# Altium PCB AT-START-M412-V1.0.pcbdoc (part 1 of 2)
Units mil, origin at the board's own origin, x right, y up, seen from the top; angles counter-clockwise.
Board outline 4079.45 x 3617.4 mil, 2 copper layers (Top Layer, Bottom Layer); 111 components, 104 nets, 441 pads, 691 vias.
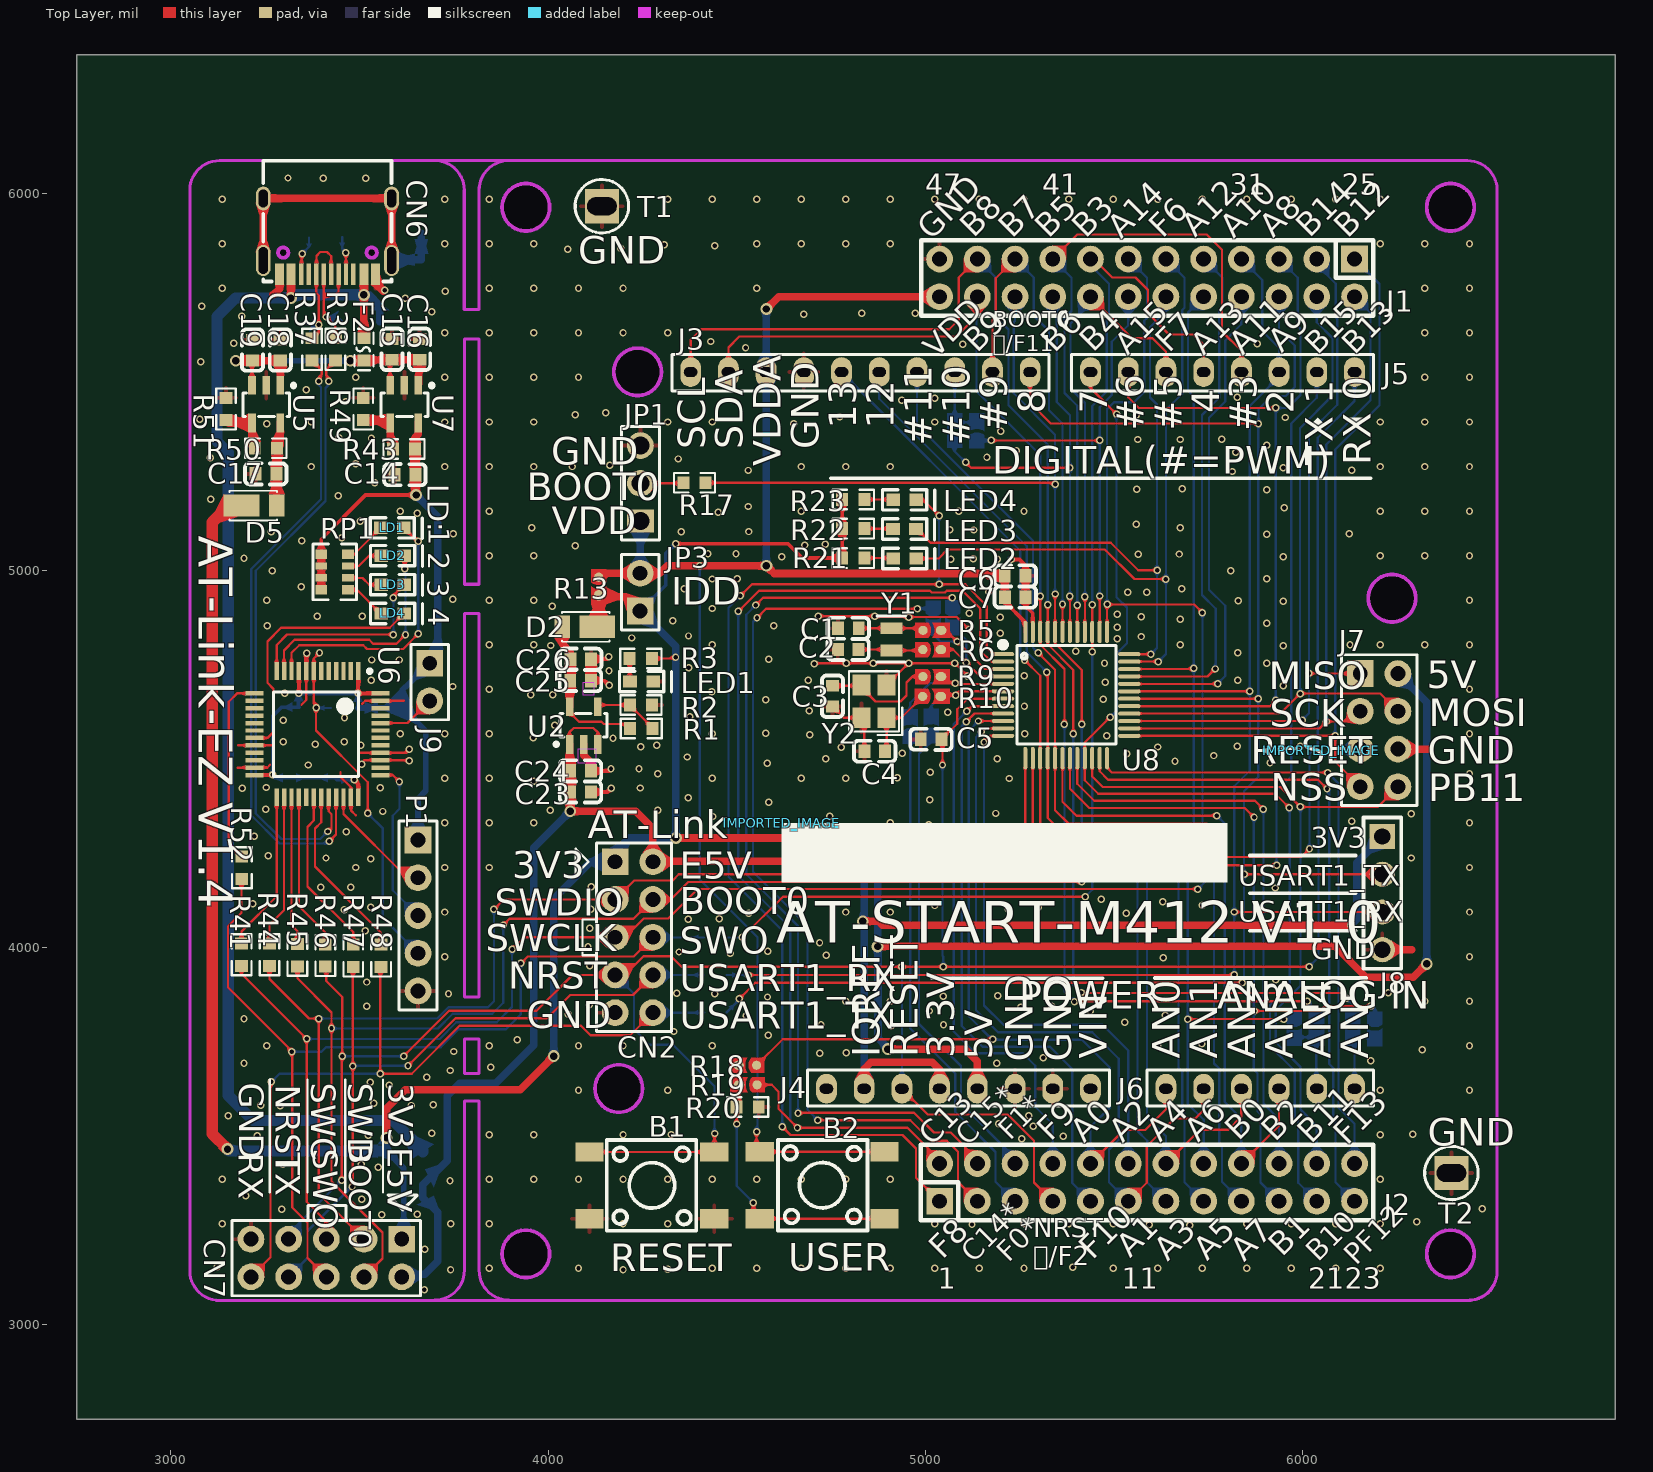
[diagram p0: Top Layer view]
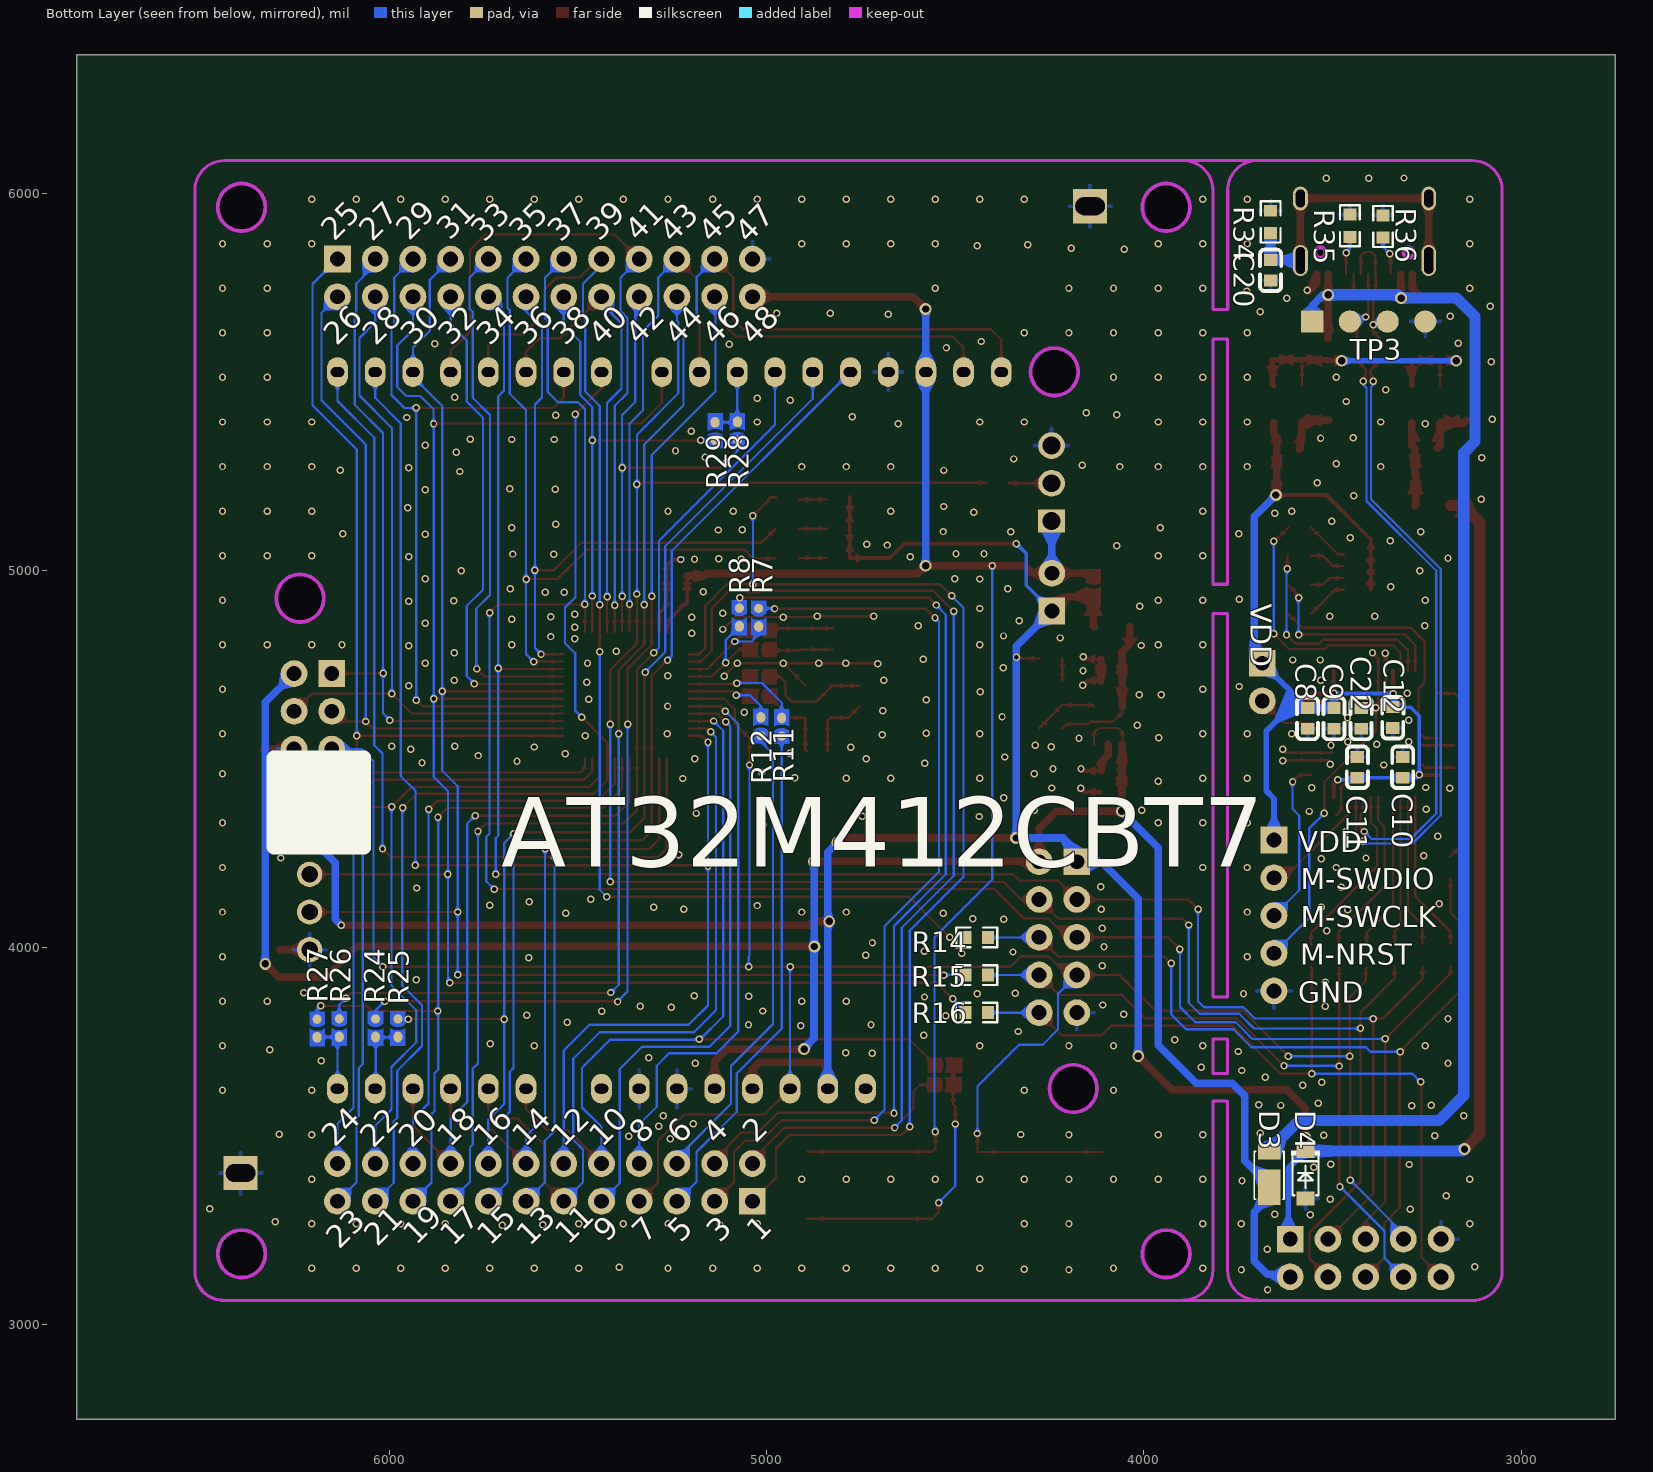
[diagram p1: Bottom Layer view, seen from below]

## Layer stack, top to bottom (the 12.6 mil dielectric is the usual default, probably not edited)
Top Layer: signal copper (thickness not stored)
Dielectric: dielectric 12.6, FR-4, Dk 4.8
Bottom Layer: signal copper (thickness not stored)

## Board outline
6829.45,2750 2750,2750 2750,6367.4 6829.45,6367.4
cut-out: 6455.12,5962.67 ccw(c6392.12,5962.67) 6329.13,5962.67 ccw(c6392.12,5962.67)
cut-out: 6455.12,3187.98 ccw(c6392.12,3187.98) 6329.13,3187.98 ccw(c6392.12,3187.98)
cut-out: 4003.92,3187.98 ccw(c3940.92,3187.98) 3877.93,3187.98 ccw(c3940.92,3187.98)
cut-out: 4250.26,3626.35 ccw(c4187.26,3626.35) 4124.27,3626.35 ccw(c4187.26,3626.35)
cut-out: 6300.26,4926.35 ccw(c6237.27,4925.79) 6174.28,4926.35 ccw(c6237.27,4926.91)
cut-out: 4300.26,5526.35 ccw(c4237.26,5526.35) 4174.27,5526.35 ccw(c4237.26,5526.35)
cut-out: 4003.93,5962.67 ccw(c3940.94,5962.44) 3877.95,5962.67 ccw(c3940.94,5962.89)

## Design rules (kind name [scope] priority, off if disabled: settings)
Clearance copperThickness1oz [All] p1: gap=7 ignorepadtopadclearanceinfootprint=FALSE except(6: Track-Track Track-SMDPad SMDPad-SMDPad Track-THPad SMDPad-THPad THPad-THPad Track-Via SMDPad-Via THPad-Via Via-Via Track-Fill SMDPad-Fill THPad-Fill Via-Fill Fill-Fill SMDPad-Region THPad-Region Via-Region Fill-Region Region-Region Track-Poly SMDPad-Poly THPad-Poly Via-Poly Fill-Poly Poly-Poly Track-Text SMDPad-Text THPad-Text Via-Text Fill-Text Region-Text Poly-Text Text-Text Track-Hole SMDPad-Hole THPad-Hole Via-Hole Fill-Hole Region-Hole Poly-Hole Text-Hole; 11.8: Track-Region Region-Poly Track-Sheet SMDPad-Sheet THPad-Sheet Via-Sheet Fill-Sheet Region-Sheet Poly-Sheet Text-Sheet Sheet-Hole)
DiffPairsRouting differentialPair [All] p1: maxuncoupledlength=10 maxlimit=6 mostfreqgap=6 toplayer_minwidth=5 toplayer_prefwidth=10 toplayer_maxwidth=100 bottomlayer_minwidth=5 bottomlayer_prefwidth=10 bottomlayer_maxwidth=100
PasteMaskExpansion pasteMaskExpansion [All] p1:
PlaneConnect innerPlane [All] p1: planeconnectstyle=Relief reliefexpansion=20 reliefentries=4 reliefconductorwidth=10 reliefairgap=10
PolygonConnect copperRegion [All] p1: connectstyle=Relief reliefentries=4 reliefconductorwidth=10 polygonreliefangle="90 Angle" airgapwidth=10
RoutingVias viaSize [All] p1: viastyle="Through Hole" holewidth=11.8 minholewidth=11.8 maxholewidth=27.6 width=19.7 minwidth=19.7 maxwidth=39.4
SolderMaskExpansion solderMaskExpansion [All] p1: useseparateexpansions=TRUE expansion=2 expansionbottom=2
Width copperThickness1oz [All] p1: maxlimit=100 minlimit=5 preferedwidth=6

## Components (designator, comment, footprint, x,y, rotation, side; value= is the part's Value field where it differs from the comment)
B1 "TS-1002S-05026C" KEY-SMD_4P-L6.0-W6.0-P4.50-LS9.0 4275.36,3369.64 r0 top
B2 "TSA063G60-250" KEY-SMD_4P-L6.1-W6.1-P4.50-LS9.0 4726.55,3369.99 r180 top
C1 "CL10C180JB8NNNC" C0603 4796.08,4846.54 r0 top
C2 "CL10C180JB8NNNC" C0603 4795.58,4790.46 r0 top
C3 "CL10C150JB8NNNC" C0603 4753.97,4666.49 r90 top
C4 "CL10C150JB8NNNC" C0603 4865.97,4520.49 r0 top
C5 "CC0603KRX7R9BB104" C0603 5015.49,4552.03 r0 top
C6 "CL10A475KO8NNNC" C0603 5238.29,4985.83 r180 top
C7 "CC0603KRX7R9BB104" C0603 5238.35,4929.24 r180 top
C8 "CL10A475KO8NNNC" C0603 3565.92,4607.82 r90 bottom
C9 "CC0603KRX7R9BB104" C0603 3495.92,4607.82 r90 bottom
C10 "CC0603KRX7R9BB104" C0603 3313.92,4477.82 r270 bottom
C11 "CC0603KRX7R9BB104" C0603 3433.92,4477.82 r270 bottom
C12 "CC0603KRX7R9BB104" C0603 3339.92,4609.82 r90 bottom
C14 "CL10A106KP8NNNC" C0603 3620.53,5253.61 r0 top
C15 "CL10A106KP8NNNC" C0603 3586.1,5585.92 r270 top
C16 "CC0603KRX7R9BB104" C0603 3659.3,5585.96 r270 top
C17 "CL10A106KP8NNNC" C0603 3251.92,5255.82 r0 top
C18 "CL10A106KP8NNNC" C0603 3290.1,5583.92 r270 top
C19 "CC0603KRX7R9BB104" C0603 3216.1,5583.92 r270 top
C20 "CC0603KRX7R9BB104" C0603 3663.92,5795.82 r90 bottom
C22 "CC0603KRX7R9BB104" C0603 3423.92,4607.82 r90 bottom
C23 "CL10A106KP8NNNC" C0603 4085.97,4412.49 r0 top
C24 "CC0603KRX7R9BB104" C0603 4085.97,4468.49 r0 top
C25 "CL10A106KP8NNNC" C0603 4086.25,4707.66 r0 top
C26 "CC0603KRX7R9BB104" C0603 4086.58,4764.74 r0 top
CN2 "CON10" HDR2X5 4177.67,4227.53 r270 top
CN6 "TYPEC-304-BCP16" USB-C-SMD_TYPEC-304-BCP16 3414.92,5885.82 r180 top
CN7 "CON10" HDR2X5 3612.1,3227.03 r180 top locked
D2 "DFLS130L-7" POWERDI-123_L2.8-W1.8-LS3.7-RD 4083.97,4850.49 r180 top
D3 "DFLS130L-7" POWERDI-123_L2.8-W1.8-LS3.7-RD 3667.92,3411.82 r90 bottom
D4 "SMF3.3A_C2759873" SOD-123FL_L2.8-W1.8-LS3.8-RD 3571.62,3397.74 r270 bottom
D5 "DFLS130L-7" POWERDI-123_L2.8-W1.8-LS3.7-RD 3233.92,5171.82 r0 top
F2 "BSMD0603-050-6V" F0603 3511.92,5585.82 r270 top
IMPORTED_IMAGE "IMPORTED_IMAGE" IMPORTED_IMAGE 6049.2,4522.45 r0 top
IMPORTED_IMAGE "IMPORTED_IMAGE" IMPORTED_IMAGE 4619.97,4329.49 r0 top
J1 "Header 12X2" HEAD2*12 6137.91,5825.49 r180 top locked
J2 "Header 12X2" HEAD2*12 5037.93,3327.39 r0 top locked
J3 "CON10" "HDR1X10 - 2#" 5277.93,5525.82 r180 top locked
J4 "CON8" "HDR1X8 - 2#" 4737.93,3625.82 r0 top locked
J5 "CON8" "HDR1X8 - 2#" 6137.93,5525.82 r180 top locked
J6 "CON6" "HDR1X6 -2#" 5637.93,3625.82 r0 top locked
J7 "Header 4X2" HDR2X4 6152.93,4726.39 r270 top locked
J8 "PZ2.54-1*4-WZ" HDR-TH_4P-P2.54-H-M-W7.7-P 6211.54,4144.37 r270 top locked
J9 "1X2P_2.54M" HDR1X2 3686.1,4754.03 r270 top
JP1 "2.54-1*3P针" HDR-TH_3P-P2.54-V-M-1 4244.82,5230.95 r90 top
JP3 "1X2P_2.54M" HDR1X2 4243.97,4892.49 r90 top
LD1 "RED" LED0603 3556.14,5112.82 r0 top
LD2 "GREEN" LED0603 3557.1,5038.72 r0 top
LD3 "BLUE" LED0603 3557.14,4961.82 r0 top
LD4 "YELLOW" LED0603 3557.1,4885.82 r0 top
LED1 "RED" LED0603 4217.22,4705.31 r0 top
LED2 "RED" LED0603 4914.8,5031.55 r0 top
LED3 "YELLOW" LED0603 4914.43,5109.54 r0 top
LED4 "GREEN" LED0603 4914.61,5187.03 r0 top
P1 "Header 5" HDR1X5 3655.1,4285.03 r270 top
R1 "0603WAF5102T5E" R0603 4246.78,4580.68 r0 top
R2 "0603WAF1502T5E" R0603 4246.14,4642.98 r0 top
R3 "0603WAF1001T5E" R0603 4245.97,4766.49 r0 top
R5 "0603WAF0000T5E" SB-PAD_2 5019.42,4841.02 r0 top
R6 "0603WAF0000T5E" SB-PAD_2 5018.84,4789.96 r0 top
R7 "SB_PAD" SB-PAD_2 5021.33,4873.81 r270 bottom
R8 "SB_PAD" SB-PAD_2 5072.35,4874.25 r270 bottom
R9 "0603WAF0000T5E" SB-PAD_2 5019.02,4718.48 r0 top
R10 "0603WAF0000T5E" SB-PAD_2 5018.49,4665.95 r0 top
R11 "SB_PAD" SB-PAD_2 4960.34,4586.25 r90 bottom
R12 "SB_PAD" SB-PAD_2 5015.44,4587.74 r90 bottom
R13 "0603WAF0000T5E" SB-PAD_2 4133.97,4956.49 r270 top
R14 "0603WAF4700T5E" R0603 4443.07,4026.98 r180 bottom
R15 "0603WAF4700T5E" R0603 4443.1,3927.07 r180 bottom
R16 "0603WAF4700T5E" R0603 4443.46,3828.11 r180 bottom
R17 "0603WAF3301T5E" R0603 4387.97,5232.49 r180 top
R18 "0603WAF0000T5E" SB-PAD_2 4527.17,3688.08 r180 top
R19 "SB_PAD" SB-PAD_2 4528.62,3636.15 r180 top
R20 "0603WAF1003T5E" R0603 4528.75,3577.36 r0 top
R21 "0603WAF1001T5E" R0603 4809.4,5032.65 r180 top
R22 "0603WAF1001T5E" R0603 4809.4,5110.65 r180 top
R23 "0603WAF1001T5E" R0603 4809.4,5188.14 r180 top
R24 "SB_PAD" SB-PAD_2 6036.99,3785.48 r270 bottom
R25 "0603WAF0000T5E" SB-PAD_2 5977.56,3785.51 r270 bottom
R26 "SB_PAD" SB-PAD_2 6133.09,3785.81 r270 bottom
R27 "0603WAF0000T5E" SB-PAD_2 6192.02,3784.58 r270 bottom
R28 "SB_PAD" SB-PAD_2 5077.61,5371.23 r90 bottom
R29 "0603WAF0000T5E" SB-PAD_2 5136.87,5370.02 r90 bottom
R34 "RC0603FR-071ML" R0603 3663.92,5923.82 r90 bottom
R35 "0603WAF5101T5E" R0603 3453.92,5913.82 r90 bottom
R36 "0603WAF5101T5E" R0603 3365.92,5911.82 r90 bottom
R37 "0603WAF0000T5E" R0603 3373.92,5585.82 r270 top
R38 "0603WAF0000T5E" R0603 3435.92,5585.82 r270 top
R41 "0603WAF330JT5E" R0603 3187.3,3981.07 r270 top
R43 "0603WAF4702T5E" R0603 3617.92,5321.82 r180 top
R44 "0603WAF330JT5E" R0603 3261.3,3981.07 r270 top
R45 "0603WAF330JT5E" R0603 3335.3,3980.07 r270 top
R46 "0603WAF330JT5E" R0603 3409.3,3979.07 r270 top
R47 "0603WAF330JT5E" R0603 3483.3,3978.07 r270 top
R48 "0603WAF330JT5E" R0603 3557.3,3978.07 r270 top
R49 "0603WAF1502T5E" R0603 3509.92,5427.82 r90 top
R50 "0603WAF5102T5E" R0603 3251.92,5323.82 r180 top
R51 "0603WAF1502T5E" R0603 3145.92,5427.82 r90 top
R52 "0603WAF330JT5E" R0603 3187.92,4211.82 r270 top
RP1 "4D03WGJ0102T5E" RES-ARRAY-SMD_0603-8P-L3.2-W1.6-BL 3433.92,4995.82 r270 top
T1 "Test point" TestPoint 4142.64,5965.57 r0 top
T2 "Test point" TestPoint 6394.79,3402.35 r0 top
TP3 "1X4P_2.54F" "HDR1X4 - TOP" 3553.92,5659.82 r0 bottom
U2 "RT9080N-08GJ5" SOT-23-5 4157,4603.45 r90 top
U5 "RT9080N-08GJ5" SOT-23-5 3189.92,5425.82 r270 top
U6 "AT32F403ACCT7" "LQFP48 - 2" 3496.84,4733.03 r270 top locked
U7 "RT9080N-08GJ5" SOT-23-5 3555.92,5425.82 r270 top
U8 "AT32M412CxT7" LQFP-48_L7.0-W7.0-P0.50-LS9.0-BL 5373.54,4669.59 r270 top locked
Y1 "32.768KHz" "XTAL_SOP - FC-12M" 4910.33,4846.79 r270 top
Y2 "CJ13-080001210B20" CRYSTAL-SMD_4P-L3.2-W2.5-BL 4863.97,4652.49 r90 top

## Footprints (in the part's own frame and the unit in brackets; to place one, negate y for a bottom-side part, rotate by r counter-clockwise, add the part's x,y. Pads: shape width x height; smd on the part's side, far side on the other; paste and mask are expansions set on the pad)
C0603 [mm]
  rect 0.8x0.9 smd: 1(-0.7,0) 2(0.7,0)
  silkscreen extent -1.41,-0.71 1.39,0.72
CRYSTAL-SMD_4P-L3.2-W2.5-BL [mm]
  rect 1.4x1.2 smd: 1(-1.1,-0.85) 2(1.1,-0.85) 3(1.1,0.85) 4(-1.1,0.85)
  silkscreen extent -2.26,-1.91 2.03,1.68
F0603 [mil]
  rect 31.75x34.02 smd: 1(-29.66,0) 2(29.66,0)
  silkscreen extent -55,-25 55,25
HDR1X2 [mm]
  rect 1.8x1.8 hole 1: 1(0,0)
  round 1.8 hole 1: 2(2.54,0)
  silkscreen extent -1.27,-1.27 3.81,1.27
"HDR1X4 - TOP" [mm]
  rect 1.5x1.5 smd: 1(0,0)
  round 1.5 smd: 2(-2.54,0) 3(-5.08,0) 4(-7.62,0)
HDR1X5 [mm]
  rect 1.8x1.8 hole 1: 1(0,0)
  round 1.8 hole 1: 2(2.54,0) 3(5.08,0) 4(7.62,0) 5(10.16,0)
  silkscreen extent -1.27,-1.27 11.43,1.27
"HDR1X6 -2#" [mm]
  oval 1.4x2 hole 0.65 slot 0.9 at 0 deg: 1(0,0) 2(2.54,0) 3(5.08,0) 4(7.62,0) 5(10.16,0) 6(12.7,0)
  silkscreen extent -1.27,-1.17 13.97,1.27
"HDR1X8 - 2#" [mm]
  oval 1.4x2 hole 0.65 slot 0.9 at 0 deg: 1(0,0) 2(2.54,0) 3(5.08,0) 4(7.62,0) 5(10.16,0) 6(12.7,0) 7(15.24,0) 8(17.78,0)
  silkscreen extent -1.27,-1.17 19.05,1.27
"HDR1X10 - 2#" [mm]
  oval 1.4x2 hole 0.65 slot 0.9 at 0 deg: 1(0,0) 2(2.54,0) 3(5.08,0) 4(7.62,0) 5(10.16,0) 6(12.7,0) 7(15.24,0) 8(17.78,0) 9(20.32,0) 10(22.86,0)
  silkscreen extent -1.27,-1.17 24.1,1.27
HDR2X4 [mm]
  rect 1.8x1.8 hole 1: 1(0,0)
  round 1.8 hole 1: 2(0,2.54) 3(2.54,0) 4(2.54,2.54) 5(5.08,0) 6(5.08,2.54) 7(7.62,0) 8(7.62,2.54)
  silkscreen extent -1.27,-1.27 8.89,3.81
HDR2X5 [mm]
  rect 1.8x1.8 hole 1: 1(0,0)
  round 1.8 hole 1: 2(0,2.54) 3(2.54,0) 4(2.54,2.54) 5(5.08,0) 6(5.08,2.54) 7(7.62,0) 8(7.62,2.54) 9(10.16,0) 10(10.16,2.54)
  silkscreen extent -1.27,-1.27 11.43,3.81
HDR-TH_3P-P2.54-V-M-1 [mm]
  rect 1.575x1.8 hole 1.2: 1(-2.54,0)
  round 1.8 hole 1.2: 2(0,0) 3(2.54,0)
  silkscreen extent -3.81,-1.27 3.81,1.27
HDR-TH_4P-P2.54-H-M-W7.7-P [mm]
  rect 1.7x1.7 hole 1.1: 1(-3.81,0)
  round 1.7 hole 1.1: 2(-1.27,0) 3(1.27,0) 4(3.81,0)
  silkscreen extent -5.09,-1.27 5.09,1.27
HEAD2*12 [mm]
  rect 1.8x1.8 hole 1: 1(0,0)
  round 1.8 hole 1: 2(0,2.54) 3(2.54,0) 4(2.54,2.54) 5(5.08,0) 6(5.08,2.54) 7(7.62,0) 8(7.62,2.54) 9(10.16,0) 10(10.16,2.54) 11(12.7,0) 12(12.7,2.54) 13(15.24,0) 14(15.24,2.54) 15(17.78,0) 16(17.78,2.54) 17(20.32,0) 18(20.32,2.54) 19(22.86,0) 20(22.86,2.54) 21(25.4,0) 22(25.4,2.54) 23(27.94,0) 24(27.94,2.54)
  silkscreen extent -1.27,-1.27 29.19,3.81
IMPORTED_IMAGE [mil]
KEY-SMD_4P-L6.0-W6.0-P4.50-LS9.0 [mm]
  rect 1.9x1.3 smd: 1(-4.2,2.25) 2(4.2,2.25) 3(-4.2,-2.25) 4(4.2,-2.25)
  silkscreen extent -3.05,-3.05 2.98,3.05
KEY-SMD_4P-L6.1-W6.1-P4.50-LS9.0 [mm]
  rect 1.9x1.3 smd: 1(-4.2,2.25) 2(4.2,2.25) 3(-4.2,-2.25) 4(4.2,-2.25)
  silkscreen extent -3.05,-3.05 2.98,3.05
LED0603 [mil]
  rect 36x32 smd: 1(-0.04,0.2) 2(60.96,0.2)
  silkscreen extent -28,-28 110,27
"LQFP48 - 2" [mm]
  rect 1.2x0.3 smd: 1(0,0) 2(0,-0.5) 3(0,-1) 4(0,-1.5) 5(0,-2) 6(0,-2.5) 7(0,-3) 8(0,-3.5) 9(0,-4) 10(0,-4.5) 11(0,-5) 12(0,-5.5) 25(8.5,-5.5) 26(8.5,-5) 27(8.5,-4.5) 28(8.5,-4) 29(8.5,-3.5) 30(8.5,-3) 31(8.5,-2.5) 32(8.5,-2) 33(8.5,-1.5) 34(8.5,-1) 35(8.5,-0.5) 36(8.5,0)
  rect 0.3x1.2 smd: 13(1.5,-7) 14(2,-7) 15(2.5,-7) 16(3,-7) 17(3.5,-7) 18(4,-7) 19(4.5,-7) 20(5,-7) 21(5.5,-7) 22(6,-7) 23(6.5,-7) 24(7,-7) 37(7,1.5) 38(6.5,1.5) 39(6,1.5) 40(5.5,1.5) 41(5,1.5) 42(4.5,1.5) 43(4,1.5) 44(3.5,1.5) 45(3,1.5) 46(2.5,1.5) 47(2,1.5) 48(1.5,1.5)
  silkscreen extent -0.12,-5.71 7.11,0.89
LQFP-48_L7.0-W7.0-P0.50-LS9.0-BL [mil]
  oval 10.6x59.1 smd: 1(-108.3,-167.3) 2(-88.6,-167.3) 3(-68.9,-167.3) 4(-49.2,-167.3) 5(-29.5,-167.3) 6(-9.8,-167.3) 7(9.8,-167.3) 8(29.5,-167.3) 9(49.2,-167.3) 10(68.9,-167.3) 11(88.6,-167.3) 12(108.3,-167.3) 25(108.3,167.3) 26(88.6,167.3) 27(68.9,167.3) 28(49.2,167.3) 29(29.5,167.3) 30(9.8,167.3) 31(-9.8,167.3) 32(-29.5,167.3) 33(-49.2,167.3) 34(-68.9,167.3) 35(-88.6,167.3) 36(-108.3,167.3)
  oval 59.1x10.6 smd: 13(167.3,-108.3) 14(167.3,-88.6) 15(167.3,-68.9) 16(167.3,-49.2) 17(167.3,-29.5) 18(167.3,-9.8) 19(167.3,9.8) 20(167.3,29.5) 21(167.3,49.2) 22(167.3,68.9) 23(167.3,88.6) 24(167.3,108.3) 37(-167.3,108.3) 38(-167.3,88.6) 39(-167.3,68.9) 40(-167.3,49.2) 41(-167.3,29.5) 42(-167.3,9.8) 43(-167.3,-9.8) 44(-167.3,-29.5) 45(-167.3,-49.2) 46(-167.3,-68.9) 47(-167.3,-88.6) 48(-167.3,-108.3)
  silkscreen extent -141,-176 130,132
POWERDI-123_L2.8-W1.8-LS3.7-RD [mm]
  rect 2.4x1.5 smd: 1(-1.187,0)
  rect 1.05x1.5 smd: 2(1.187,0)
  silkscreen extent -2,-1 1.2,1
R0603 [mil]
  rect 31.75x34.02 smd: 1(-29.66,0) 2(29.66,0)
  silkscreen extent -55,-26 55,26
RES-ARRAY-SMD_0603-8P-L3.2-W1.6-BL [mm]
  rect 0.65x0.8 smd: 1(-1.2,-0.9) 4(1.2,-0.9) 5(1.2,0.9) 8(-1.2,0.9)
  rect 0.5x0.8 smd: 2(-0.4,-0.9) 3(0.4,-0.9) 6(0.4,0.9) 7(-0.4,0.9)
  silkscreen extent -1.87,-1.45 1.87,1.47
SB-PAD_2 [mil]
  oval 24.6x24 smd: 1(-25.5,0)
  oval 28.2x24 smd: 2(22.5,0)
  Top Layer region: -46,20 -12,20 -6.82,12.19 -5,3 -5,3 -5,-3 -6.82,-12.19 -12,-20 -12,-20 -46,-20
  Top Layer region: -1,20 3.47,12.03 5.01,3.03 5.01,3.02 5.01,-2.98 3.47,-12.01 -1,-20 -1,-20 46,-20 46,20
SOD-123FL_L2.8-W1.8-LS3.8-RD [mm]
  rect 0.93x1.2 smd: 1(-1.6,0) 2(1.6,0)
  silkscreen extent -1.6,-0.95 1.38,0.95
SOT-23-5 [mil]
  rect 50x20 smd: 1(-65,100) 2(-65,63) 3(-65,25) 4(35,25) 5(35,100)
  silkscreen extent -65,1 18,135
TestPoint [mm]
  rect 2.3x2.3 hole 1.2 slot 2 at 0 deg: 1(0,0)
  silkscreen extent -1.8,-1.8 1.8,1.8
USB-C-SMD_TYPEC-304-BCP16 [mil]
  oval 39.4x82.7 hole 23.6 slot 70.9 at 90 deg: 13(-170.1,64.3) 14(170.1,64.3)
  oval 39.4x63 hole 23.6 slot 47.2 at 90 deg: 15(-170.1,-100.3) 16(170.1,-100.3)
  rect 23.6x57.1 smd: A1B12(-127,100.3) A4B9(-96.5,100.3) B1A12(126.8,100.3) B4A9(96.5,100.3)
  rect 11.8x57.1 smd: A5(-49.2,100.3) A6(-9.8,100.3) A7(9.8,100.3) A8(49.2,100.3) B5(68.9,100.3) B6(29.5,100.3) B7(-29.5,100.3) B8(-68.9,100.3)
  Multi-Layer board cut-out: 103.5,43.4 105.35,36.5 110.4,31.45 117.3,29.6 124.2,31.45 129.26,36.5 131.1,43.4 131.1,43.4 129.74,49.39 125.91,54.19 120.37,56.86 114.23,56.86 108.7,54.19 104.87,49.39 103.5,43.4
  Multi-Layer board cut-out: -131.1,43.4 -129.25,36.5 -124.2,31.45 -117.3,29.6 -110.4,31.45 -105.34,36.5 -103.5,43.4 -103.5,43.4 -104.86,49.39 -108.69,54.19 -114.23,56.86 -120.37,56.86 -125.9,54.19 -129.73,49.39 -131.1,43.4
  Multi-Layer keep-out circle w10: c117.3,43.4 r13.8
  Multi-Layer keep-out circle w10: c-117.3,43.4 r13.8
  silkscreen extent -170,-200 170,120
"XTAL_SOP - FC-12M" [mm]
  rect 0.8x1.5 smd: 1(0,0) 2(1.5,0)
  silkscreen extent -0.81,-0.99 2.29,0.94

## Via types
v1: diameter 19.68, hole 11.81, Top Layer to Bottom Layer, 340 vias
v2: diameter 19.7, hole 11.81, Top Layer to Bottom Layer, 266 vias
v3: diameter 19.7, hole 11.8, Top Layer to Bottom Layer, 67 vias
v4: diameter 31.5, hole 19.68, Top Layer to Bottom Layer, 18 vias

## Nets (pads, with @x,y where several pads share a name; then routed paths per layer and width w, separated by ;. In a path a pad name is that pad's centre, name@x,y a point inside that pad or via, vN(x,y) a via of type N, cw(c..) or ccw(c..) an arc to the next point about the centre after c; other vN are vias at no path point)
3V3: CN2.1 CN7.1 D2.1 D4.1 D5.1 J4.2 J4.4 J8.1 JP3.1 R3.2 R13.2 R21.2 R22.2 R23.2 | length 8670.7
  Top Layer w6: R3.2@4275.63,4766.49 4334.18,4766.49 v1(4337.78,4770.08)
  Top Layer w10: v3(4337.97,5070.49) 4635.97,5070.49 4673.81,5032.65 R21.2@4779.74,5032.65 R22.2@4779.74,5110.65 R23.2@4779.74,5194.65
  Top Layer w20: v4(3571.92,3495.39) 3571.92,3573.75 3621.61,3623.44 3926.07,3623.44 v4(4015.07,3712.44) ; D2.1@4130.72,4850.49 4133.97,4853.74 R13.2@4133.97,4933.99 4137.47,4930.49 4205.97,4930.49 JP3.1@4243.97,4892.49 ; v4(4338.67,4290.58) 4800.53,4290.58 v4(4812.37,4278.74) ; v4(4834.19,4069.44) 4876.13,4069.44 4885.76,4059.81 v3(6128.31,4059.81) ; J4.2@4837.93,3625.82 4837.93,3678.13 4855.64,3695.85 5018.49,3695.85 5037.93,3676.41 J4.4@5037.93,3625.82
  Top Layer w30: v4(3149.92,3465.82) 3109.62,3506.12 3109.62,5127.51 3153.92,5171.82 D5.1@3187.17,5171.82
  Bottom Layer w10: JP3.1@4243.97,4892.49 4311.97,4960.49 4311.97,5044.49 v3(4337.97,5070.49)
  Bottom Layer w15: D4.1@3571.62,3460.73 3617.4,3414.95 3617.4,3232.32 CN7.1@3612.1,3227.03
  Bottom Layer w20: D4.1@3571.62,3460.73 3571.92,3461.03 v4(3571.92,3495.39) ; v4(4015.07,3712.44) 4015.07,4129.63 4112.97,4227.53 CN2.1@4177.67,4227.53 4177.67,4253.94 4214.31,4290.58 v4(4338.67,4290.58) 4338.67,4769.19 v1(4337.78,4770.08) 4337.78,4798.68 JP3.1@4243.97,4892.49 ; v4(4812.37,4278.74) 4837.93,4253.18 4837.93,4047.53 4837.52,4047.12 4837.52,3626.23 J4.2@4837.93,3625.82 ; v3(6128.31,4059.81) 6144.13,4075.63 6144.13,4225.11 6211.54,4292.51 J8.1@6211.54,4294.37
  Bottom Layer w30: v4(3149.92,3465.82) 3155.01,3460.73 D4.1@3571.62,3460.73
$1N792: LD1.1 RP1.8 | length 115.7
  Top Layer w6: RP1.8@3469.36,5043.06 3486.13,5043.06 LD1.1@3556.1,5113.03
$1N793: LD2.1 RP1.7 | length 99
  Top Layer w6: RP1.7@3469.36,5011.57 3497.67,5011.57 3525.04,5038.93 LD2.1@3557.06,5038.93
$1N794: LD3.1 RP1.6 | length 95.2
  Top Layer w6: RP1.6@3469.36,4980.07 3507.67,4980.07 3525.72,4962.03 LD3.1@3557.1,4962.03
$1N795: LD4.1 RP1.5 | length 113.6
  Top Layer w6: RP1.5@3469.36,4948.58 3493.16,4948.58 3555.72,4886.03 LD4.1@3557.06,4886.03
$1N16959: C15.2 C16.2 C18.2 C19.2 F2.2 U5.1 U5.3 U7.1 U7.3 | length 876.6
  Top Layer w6: U5.3@3214.92,5490.82 3214.92,5555.18 C19.2@3215.56,5555.82 ; U7.3@3580.92,5490.82 3580.92,5553.18 C15.2@3586.1,5558.36
  Top Layer w15: v4(3171.92,5555.82) C19.2@3215.56,5555.82 ; C19.2@3216.1,5556.36 C19.2@3215.56,5555.82 ; U5.1@3289.92,5490.82 3289.92,5555.46 C18.2@3289.56,5555.82 ; C18.2@3290.1,5556.36 C18.2@3289.56,5555.82 ; v4(3475.92,5555.82) 3476.26,5556.16 F2.2@3511.92,5556.16 3514.12,5558.36 C15.2@3586.1,5558.36 C16.2@3659.3,5558.4 ; U7.1@3655.92,5490.82 3659.3,5494.2 C16.2@3659.3,5558.4 ; C19.2@3215.56,5555.82 C18.2@3289.56,5555.82
  Bottom Layer w15: v4(3171.92,5555.82) v4(3475.92,5555.82)
$1N17598: R43.2 R49.1 U7.4 | length 146.1
  Top Layer w20: R49.1@3509.92,5398.16 3573.58,5398.16 U7.4@3580.92,5390.82 3580.92,5354.82 3585.92,5349.82 3585.92,5324.16 R43.2@3588.26,5321.82
$1N17675: R50.2 R51.1 U5.4 | length 142.1
  Top Layer w20: R51.1@3145.92,5398.16 3153.26,5390.82 U5.4@3214.92,5390.82 3214.92,5331.16 R50.2@3222.26,5323.82
$2N438: C2.2 R6.1 Y1.2 | length 172.2
  Top Layer w6: C2.2@4823.14,4790.46 4907.6,4790.46 Y1.2@4910.33,4787.73 4991.11,4787.73 R6.1@4993.34,4789.96
$2N5937: R9.2 R11.2 U8.5 | length 354.5
  Top Layer w6: R9.2@5041.52,4718.48 5041.52,4717.83 5058.08,4701.27 v2(5079.84,4701.27) 5082.01,4699.09 U8.5@5206.24,4699.09
  Bottom Layer w6: R11.2@4960.34,4608.75 4960.34,4648.92 5012.69,4701.27 v2(5079.84,4701.27)
$2N5955: R10.2 R12.2 U8.6 | length 278.6
  Top Layer w6: R10.2@5040.99,4665.95 5045.31,4670.27 5078.72,4670.27 v2(5080.18,4668.81) 5090.76,4679.39 U8.6@5206.24,4679.39
  Bottom Layer w6: R12.2@5015.44,4610.24 5015.44,4640.29 5043.96,4668.81 v2(5080.18,4668.81)
$2N5975: C1.2 R5.1 Y1.1 | length 172.8
  Top Layer w6: C1.2@4823.64,4846.54 4910.08,4846.54 Y1.1@4910.33,4846.79 4988.15,4846.79 R5.1@4993.92,4841.02
$2N6104: R5.2 R7.2 U8.3 | length 299.5
  Top Layer w6: R5.2@5041.92,4841.02 5055.32,4841.02 v2(5084.81,4811.52) 5157.84,4738.49 U8.3@5206.24,4738.49
  Bottom Layer w6: R7.2@5021.33,4851.31 5021.33,4829.49 5039.29,4811.52 v2(5084.81,4811.52)
$2N6111: R6.2 R8.2 U8.4 | length 305.7
  Top Layer w6: R6.2@5041.34,4789.96 5074.21,4789.96 v2(5108.68,4755.5) 5145.38,4718.79 U8.4@5206.24,4718.79
  Bottom Layer w6: R8.2@5072.35,4851.75 5108.72,4815.38 v2(5108.68,4755.5)
$2N6210: C3.2 R9.1 Y2.3 | length 308.9
  Top Layer w6: C3.2@4753.97,4694.05 4828.76,4694.05 Y2.3@4830.51,4695.8 4830.51,4689.95 4867.97,4652.49 4933.97,4652.49 4949.97,4668.49 4949.97,4702.49 4965.96,4718.48 R9.1@4993.52,4718.48
$2N6248: C4.2 R10.1 Y2.1 | length 209.4
  Top Layer w6: C4.2@4893.53,4520.49 4897.44,4524.39 Y2.1@4897.44,4609.18 4936.22,4609.18 R10.1@4992.99,4665.95
$2N7510: JP1.2 R17.2 | length 114.1
  Top Layer w6: JP1.2@4244.82,5230.95 4356.77,5230.95 R17.2@4358.31,5232.49
$3N526: LED1.1 R3.1 | length 61.3
  Top Layer w6: R3.1@4216.31,4766.49 4216.31,4706.38 LED1.1@4217.18,4705.52
$3N6624: C25.1 C26.1 D2.2 R1.1 U2.5 | length 414.7
  Top Layer w6: U2.5@4057,4638.45 4057,4623.46 4081.97,4598.49 4141.52,4598.49 4147.52,4592.49 4205.31,4592.49 R1.1@4217.12,4580.68
  Top Layer w20: D2.2@4037.22,4850.49 4037.22,4805.24 4059.02,4783.43 C26.1@4059.02,4764.74 4057,4762.71 U2.5@4057,4638.45
$3N6989: LED2.1 R21.1 | length 76.3
  Top Layer w6: R21.1@4839.06,5032.65 4914.12,5032.65 LED2.1@4915.02,5031.75
$3N7005: LED3.1 R22.1 | length 77.5
  Top Layer w6: R22.1@4839.06,5110.65 4915.27,5110.65 LED3.1@4916.17,5109.75
$3N7010: LED4.1 R23.1 | length 75.5
  Top Layer w6: R23.1@4839.06,5188.14 4913.27,5188.14 LED4.1@4914.17,5187.24
$3N7265: R1.2 R2.1 U2.4 | length 173.5
  Top Layer w6: U2.4@4132,4638.45 4136.52,4642.98 R2.1@4216.48,4642.98 4276.44,4583.03 R1.2@4276.44,4580.68
$3N7356: B2.1 B2.2 R18.2 R19.2 R20.1 | length 766.6
  Top Layer w6: v3(4499.91,3532.38) 4499.91,3576.55 R20.1@4499.09,3577.36 4506.12,3584.4 R19.2@4506.12,3636.15 4506.12,3686.62 R18.2@4504.67,3688.08 ; v3(4544.29,3323.42) 4544.29,3298.32 B2.2@4561.2,3281.41 B2.1@4891.91,3281.41
  Bottom Layer w6: v3(4499.91,3532.38) 4499.91,3367.8 v3(4544.29,3323.42)
$4N2984: J6.5 R24.2 R25.2 | length 197.2
  Bottom Layer w6: R25.2@5977.56,3763.01 5978.33,3762.24 R24.2@6036.25,3762.24 ; R24.2@6036.99,3762.98 R24.2@6036.25,3762.24 ; J6.5@6037.93,3625.82 6036.25,3627.49 R24.2@6036.25,3762.24
$4N3391: J6.6 R26.2 R27.2 | length 198.9
  Bottom Layer w6: J6.6@6137.93,3625.82 6137.93,3758.47 R26.2@6133.09,3763.31 6190.8,3763.31 R27.2@6192.02,3762.08
$4N3469: J3.3 R28.2 R29.2 | length 194.5
  Bottom Layer w6: R28.2@5077.61,5393.73 5077.93,5394.05 R28.2@5077.93,5400.54 ; J3.3@5077.93,5525.82 R28.2@5077.93,5400.54 ; R29.2@5136.87,5392.52 5085.95,5392.52 R28.2@5077.93,5400.54
ATLINK_5V: CN6.A4B9 CN6.B4A9 D3.2 F2.1 TP3.1 | length 3402
  Top Layer w20: v4(3317.92,5721.82) 3318.42,5722.32 CN6.B4A9@3318.42,5785.52 ; CN6.A4B9@3511.42,5785.52 v4(3511.42,5730.45) 3511.42,5615.98 F2.1@3511.92,5615.48
  Bottom Layer w20: v4@3317.77,5722.16 3317.77,5721.98 v4(3317.92,5721.82) ; v4(3511.42,5730.45) 3525.3,5730.45 3553.92,5701.82 TP3.1@3553.92,5659.82
  Bottom Layer w30: v4(3511.42,5730.45) 3326.05,5730.45 3317.77,5722.16 3171.08,5722.16 3121.92,5673 3121.92,5341.67 3151.92,5311.67 3151.92,3607.82 3217.92,3541.82 3588.66,3541.82 3667.92,3462.56 D3.2@3667.92,3458.57
ATLK_BOOT0: R45.1 U6.27 | length 395.7
  Top Layer w6: U6.27@3319.67,4398.38 3319.67,4059.15 3335.1,4043.72 R45.1@3335.1,4009.03
ATLK_NRST: R46.1 U6.28 | length 419.2
  Top Layer w6: U6.28@3339.36,4398.38 3339.36,4109.89 3409.1,4040.15 R46.1@3409.1,4008.03
ATLK_RX: CN2.10 CN7.10 R16.2 R48.2 | length 2067.5
  Top Layer w6: CN7.10@3212.1,3127.03 3263.92,3178.85 3263.92,3641.82 v1(3265.92,3643.82) ; v2@3555.24,3665.79 3555.24,3946.34 R48.2@3557.3,3948.41 ; v2(3555.29,3665.74) 3638.2,3665.74 3765.32,3792.85 4087.09,3792.85 4112.1,3767.84 4217.99,3767.84 CN2.10@4277.67,3827.53
  Bottom Layer w6: v1(3265.92,3643.82) 3287.84,3665.74 v2(3555.29,3665.74) ; CN2.10@4277.67,3827.53 4413.22,3827.53 R16.2@4413.8,3828.11
ATLK_SWCLK: R41.1 U6.25 | length 427
  Top Layer w6: R41.1@3187.1,4010.03 3187.1,4042.99 3280.3,4136.2 U6.25@3280.3,4398.38
ATLK_SWDIO: R44.1 U6.26 | length 404.5
  Top Layer w6: R44.1@3261.1,4010.03 3261.1,4060.3 3299.99,4099.19 U6.26@3299.99,4398.38
ATLK_SWO: R52.1 U6.13 | length 502.2
  Top Layer w6: R52.1@3187.92,4241.48 3153.1,4276.31 3153.1,4652.04 3175.02,4673.97 U6.13@3221.25,4673.97
ATLK_TX: CN2.8 CN7.8 R15.2 R47.2 | length 1923.7
  Top Layer w6: v2(3480.15,3366.52) 3482.31,3368.67 v2(3482.31,3686.03) 3482.31,3947.41 R47.2@3483.3,3948.41 ; v1(3628.47,3686.56) 3754.42,3812.52 3996.88,3812.52 4058.93,3874.57 4224.71,3874.57 CN2.8@4277.67,3927.53
  Bottom Layer w6: CN7.8@3312.1,3127.03 3362.1,3177.03 3362.1,3248.47 v2(3480.15,3366.52) ; v2(3482.31,3686.03) 3482.84,3686.56 v1(3628.47,3686.56) ; CN2.8@4277.67,3927.53 4388.57,3927.53 4389.03,3927.07 R15.2@4413.44,3927.07
CC1: CN6.A5 R35.1 | length 102.9
  Top Layer w6: v1(3463.92,5841.82) 3464.12,5841.62 CN6.A5@3464.12,5785.52
  Bottom Layer w6: R35.1@3453.92,5884.16 3453.92,5851.82 v1(3463.92,5841.82)
CC2: CN6.B5 R36.1 | length 104.9
  Top Layer w6: CN6.B5@3346.02,5785.52 3346.02,5837.92 v1(3347.92,5839.82)
  Bottom Layer w6: v1(3347.92,5839.82) 3365.92,5857.82 R36.1@3365.92,5882.16
E5V: C23.1 C24.1 CN2.2 CN7.2 D3.1 J4.5 J7.2 U2.1 U2.3 | length 5940.3
  Top Layer w6: U2.1@4057,4538.45 4057,4571.51 4067.97,4582.49 4119.97,4582.49 4132,4570.46 U2.3@4132,4538.45
  Top Layer w20: U2.1@4057,4538.45 4057,4469.9 C24.1@4058.41,4468.49 ; v4(4873.58,4002.99) 6086.74,4002.99 6168.32,3921.41 6293.99,3921.41 v4(6329.46,3956.88) ; v4(4874.12,4228.41) 4278.55,4228.41 CN2.2@4277.67,4227.53 4277.67,4316.56 4232.8,4361.43 v4(4058.75,4361.43) 4058.41,4361.77 C23.1@4058.41,4412.49 C24.1@4058.41,4468.49 ; v4(4900.59,3730.66) 5105.75,3730.66 5137.93,3698.49 J4.5@5137.93,3625.82 ; C24.1@4058.41,4468.49 4060.6,4470.68 4062.22,4470.68 4060.04,4468.49 C24.1@4058.41,4468.49
  Bottom Layer w20: CN7.2@3612.1,3127.03 3618.89,3133.82 3672.76,3133.82 3706.81,3167.87 3706.81,3297.9 3667.92,3336.78 D3.1@3667.92,3365.07 3667.92,3370.92 3732.24,3435.24 3732.24,3606.76 3766.16,3640.67 3860.95,3640.67 3961.87,3741.59 3961.87,4264.54 v4(4058.75,4361.43) ; v4(4874.12,4228.41) 4874.12,4003.53 v4(4873.58,4002.99) 4874.6,4001.97 4874.6,3759.29 v4@4900.59,3733.3 ; v4(4900.59,3730.66) v4@4900.59,3733.3 ; v4@4902.96,3730.93 v4@4900.59,3733.3 ; J7.2@6252.93,4726.39 6329.46,4649.86 v4(6329.46,3956.88)
EGND: C20.2 CN6.13 CN6.14 CN6.15 CN6.16 R34.1 | length 819.9
  Top Layer w20: CN6.14@3244.82,5821.52 CN6.16@3244.82,5986.12 CN6.15@3585.02,5986.12 CN6.13@3585.02,5821.52
  Bottom Layer w20: CN6.13@3585.02,5821.52 3586.88,5823.38 C20.2@3663.92,5823.38 R34.1@3663.92,5894.16
GND: B1.3 B1.4 C1.1 C2.1 C3.1 C4.1 C5.1 C6.1 C7.1 C8.1 C9.1 C10.1 C11.1 C12.1 C14.1 C15.1 C16.1 C17.1 C18.1 C19.1 C20.1 C22.1 C23.2 C24.2 C25.2 C26.2 CN2.9 CN6.A1B12 CN6.B1A12 CN7.9 D4.2 J1.23 J3.7 J4.6 J4.7 J7.6 J8.4 JP1.3 LED1.2 P1.5 R2.2 R20.2 R34.2 R35.2 R36.2 R49.2 R51.2 T1.1 T2.1 TP3.4 U2.2 U5.2 U6.8 U6.20 U6.23 U6.35 U6.39 U6.40 U6.47 U7.2 U8.47 Y2.2 Y2.4 | length 2790.1
  Top Layer w6: 3177.08,4477.12 U6.23@3221.25,4477.12 3255.17,4477.12 3262.81,4484.75 ; 3178.66,4536.18 U6.20@3221.25,4536.18 3273.47,4536.18 ; 3346.33,4643.65 3359.04,4656.36 U6.8@3359.04,4733.03 ; 3449.63,4465.2 3449.63,4452.3 3477.16,4424.78 U6.35@3477.16,4398.38 3477.16,4363.64 3490.18,4350.62 ; 3500.02,4516.49 U6.40@3555.9,4516.49 3622.6,4516.49 v1(3631.92,4525.82) ; 3506.46,4645.8 3514.94,4654.29 U6.47@3555.9,4654.29 3617.03,4654.29 ; 3512.29,4496.81 U6.39@3555.9,4496.81 3630.94,4496.81 v2(3631.92,4495.82) ; v3(4705.25,4753.04) 4705.97,4753.76 v3(4790.18,4753.76) v3(4861.89,4753.76) v2@4955.4,4753.76 ; v3(4715.75,4878.79) v3(4866.25,4878.79) 4868.88,4876.16 v3(4956.33,4876.16) 5083.47,4876.16 v3(5116.22,4843.4) ; C3.1@4753.97,4638.93 4783.72,4609.18 Y2.4@4830.51,4609.18 4838.41,4601.27 C4.1@4838.41,4520.49 ; Y2.2@4897.44,4695.8 v2@4955.4,4753.76 ; v3(5112.65,4719.92) 5086.5,4746.07 5086.5,4746.49 5079.23,4753.76 v3(5077.77,4753.76) v2(4956.43,4753.76) v2@4955.4,4753.76
  Top Layer w10: U6.8@3359.04,4733.03 3359.04,4778.94 v2(3359.92,4779.82) ; C23.2@4113.53,4412.49 4157.32,4412.49 v3(4167.06,4422.23) ; C24.2@4113.53,4468.49 4161.11,4468.49 v3(4166.69,4474.06) ; C25.2@4113.81,4707.66 4149.5,4707.66 v3(4162.07,4695.08) ; C26.2@4114.14,4764.74 4154.85,4764.74 v1(4161.02,4770.91) ; v1(5227.81,5028.9) 5249.82,5028.9 5265.85,5012.87 C6.1@5265.85,4985.83 C7.1@5265.85,4929.3 ; C7.1@5265.91,4929.24 5265.91,4905.39 5284.94,4886.36 U8.47@5284.94,4836.89
  Top Layer w20: 3269.89,5730.23 3271.47,5730.23 3288.12,5746.88 CN6.B1A12@3288.12,5785.52 ; CN6.A1B12@3541.92,5785.52 3541.92,5761.94 v2@3563.18,5740.69 ; U2.2@4094,4538.45 4094,4510.46 4113.53,4490.93 C24.2@4113.53,4468.49 ; C25.2@4113.81,4707.66 4114.14,4707.99 C26.2@4114.14,4764.74 ; J8.4@6211.54,3994.37 6289.72,3994.37 6289.94,3994.58 ; J7.6@6252.93,4526.39 6332.56,4526.39 6332.71,4526.24
  Bottom Layer w10: v1@5221.26,5032.4 5224.76,5028.9 v1(5227.81,5028.9)
  other v1: 4198.61,3145.4 3741.26,3145.84 4316.72,3147.4 3844.28,3149.4 4080.5,3149.4 4434.83,3149.4 4552.94,3149.4 4671.05,3149.4 4789.16,3149.4 4907.27,3149.4 5025.38,3149.4 5143.49,3149.4 5261.6,3149.4 5497.82,3149.4 5615.93,3149.4 5734.04,3149.4 5852.15,3149.4 5970.26,3149.4 6088.37,3149.4 6206.48,3149.4 5390.37,3152.95 3123.38,3153.74 5700.88,3263.95 5123.75,3265.93 5594.02,3265.73 3135.61,3267.51 3742.15,3268.39 3844.28,3267.51 4198.61,3267.51 4316.72,3267.51 5025.38,3267.51 5261.6,3267.51 5379.71,3267.51 5497.82,3267.51 5852.15,3267.51 5970.26,3267.51 6088.37,3267.51 6206.48,3267.51 6302.59,3273.51 6476.7,3307.73 3739.85,3381.93 3135.61,3385.62 3844.28,3385.62 3962.39,3385.62 4080.5,3385.62 4198.61,3385.62 4316.72,3385.62 4434.83,3385.62 4552.94,3385.62 4671.05,3385.62 4789.16,3385.62 4907.27,3385.62 6206.48,3385.62 3844.28,3503.73 3962.39,3503.73 4198.61,3503.73 6206.48,3503.73 4326.58,3504.52 6292.62,3505.7 4080.5,3621.84 4316.72,3621.84 6206.48,3621.84 6442.7,3621.84 6317.48,3729.29 3253.72,3739.95 3844.28,3739.95 4080.5,3739.95 4198.61,3739.95 4434.83,3739.95 5615.93,3739.95 6442.7,3739.95 5732.46,3745.08 5252.72,3841.48 4789.16,3858.06 4907.27,3858.06 6324.59,3858.06 6442.7,3858.06 3726.16,3976.17 6442.7,3976.17 4719.54,4012.9 5532.5,4091.47 3726.16,4094.28 4789.16,4094.28 4907.27,4094.28 6442.7,4094.28 5219.36,4101.78 5733.89,4112.44 5628.95,4122.11 3489.94,4212.39 3726.16,4212.39 3844.28,4212.39 6442.7,4212.39 3726.16,4330.5 3844.28,4330.5 3962.39,4330.5 4907.27,4330.5 6442.7,4330.5 4005.84,4363.65 3962.39,4440.61 3726.16,4448.61 3844.28,4448.61 4434.83,4448.61 4671.05,4448.61 4789.16,4448.61 4925.27,4450.61 6442.7,4461.04 4939.27,4514.72 4777.16,4530.72 3960.39,4556.72 4694.14,4564.35 3608.05,4566.72 3726.16,4566.72 3844.28,4566.72 4434.83,4566.72 5263.37,4566.72 6442.7,4566.72 4017.17,4589.47 3954.39,4670.83 4012.13,4670.54 4434.04,4677.99 3844.28,4684.83 6442.7,4684.83 4689.2,4708.25 5262.78,4720.35 4006.5,4800.94 3844.28,4802.94 3962.39,4802.94 4434.83,4802.94 6206.48,4802.94 6324.59,4802.94 6442.7,4802.94 4330.8,4867 4434.83,4899.05 4010.44,4904.91 3253.72,4921.05 3844.28,4921.05 3962.39,4921.05 6442.7,4921.05 3844.28,5039.16 3962.39,5039.16 6206.48,5039.16 6324.59,5039.16 6442.7,5039.16 4072.21,5064.82 4353.46,5102.01 4531.49,5103.04 3956.39,5113.27 3608.05,5157.27 3844.28,5157.27 4671.05,5157.27 5261.6,5157.27 6206.48,5157.27 6324.59,5157.27 6442.7,5157.27 4530.18,5169.4 4530.3,5264.94 3371.83,5275.38 3726.16,5275.38 3844.28,5275.38 3962.39,5275.38 4063.76,5275.38 4671.05,5275.38 4789.16,5275.38 4907.27,5275.38 6206.48,5275.38 6324.59,5275.38 6442.7,5275.38 4163.35,5278.35 3489.94,5282.48 4345.54,5295.42 3254.32,5388.75 4651.51,5389.35 3371.83,5393.49 3726.16,5393.49 3844.28,5393.49 3962.39,5393.49 4316.72,5393.49 4434.83,5393.49 5025.38,5393.49 6206.48,5393.49 6324.59,5393.49 6442.7,5393.49 4773.37,5407.31 4072.3,5412.62 4152.61,5417.49 3489.94,5511.6 3726.16,5511.6 3844.28,5511.6 3962.39,5511.6 4080.5,5511.6 6324.59,5511.6 6442.7,5511.6 5879.58,5600.63 3726.16,5629.71 3844.28,5629.71 3962.39,5629.71 4080.5,5629.71 4198.61,5629.71 4316.72,5629.71 6324.59,5629.71 6442.7,5629.71 3621.67,5721.18 3727.35,5740.12 3135.61,5747.82 3844.28,5747.82 3962.39,5747.82 4080.5,5747.82 4198.61,5747.82 4552.94,5747.82 6324.59,5747.82 6442.7,5747.82 4052.5,5851.93 4192.61,5853.93 4441.93,5861.19 4308.43,5862.97 3135.61,5865.93 3726.16,5865.93 3844.28,5865.93 3962.39,5865.93 4552.94,5865.93 4671.05,5865.93 4789.16,5865.93 4907.27,5865.93 6206.48,5865.93 6324.59,5865.93 6442.7,5865.93 3135.61,5984.04 3726.16,5984.04 3844.28,5984.04 4316.72,5984.04 4434.83,5984.04 4552.94,5984.04 4671.05,5984.04 4789.16,5984.04 4907.27,5984.04 5025.38,5984.04 5143.49,5984.04 5261.6,5984.04 5379.71,5984.04 5497.82,5984.04 5615.93,5984.04 5734.04,5984.04 5852.15,5984.04 5970.26,5984.04 6088.37,5984.04 6206.48,5984.04 3310.43,6040.29
  other v2: 3672.2,3093.06 3672.47,3199.71 3559.16,3291.61 3653.25,3292.5 3294,3306.17 3506.02,3332.5 3198.63,3341.75 3549.87,3417.35 3296.17,3424.98 3504.98,3426.15 5255.54,3492.87 5365.15,3499.68 3228.92,3501.56 3522.79,3502.15 3691.11,3507.76 5285.68,3526.79 5194.13,3533.53 3152.29,3553.86 5274.63,3554.03 3289.67,3580.56 3637.43,3581.44 3237.63,3582.27 3695.65,3583.12 3538.06,3587.46 3579,3635.21 3528.58,3643.52 3678.17,3655.78 3740.98,3674.21 3847.64,3682.95 3193.72,3693.28 5189.63,3693.14 6180.37,3699.72 5312.46,3708.2 4720.65,3720.04 4790.52,3720.83 3749.27,3724.53 3918.19,3755.95 4583.61,3767.53 4333.11,3777.55 4909.63,3792.43 4723.47,3794.94 5048.18,3795.59 5528.42,3802.06 3193.72,3810.91 4525.54,3819.39 5635.59,3821.01 4052.83,3823.31 5437.72,3831.13 5010.5,3831.88 3518.6,3843.99 5335.62,3844.03 4109.25,3847.81 4581.64,3868.98 5046.99,3871.38 5192.13,3872.51 3735.9,3878.03 4441.86,3877.81 4341.2,3878.99 6227.12,3880.4 3518.6,3908.73 5928.77,3915.28 4110.1,3952.22 5630.35,3973.01 4737.82,3979.9 4483.25,3984.34 4346.94,3988.33 4582.48,3990.46 4105.76,4002.54 3514.75,4044.56 4110.5,4051.1 4371.83,4075.17 4453.27,4076.83 3459.69,4100.22 4112.47,4101.49 3530.14,4106.73 5298.87,4106.95 5025.57,4111.54 3217.09,4116.59 5466.74,4128.73 5927.98,4157.98 3476.86,4159.43 3396.66,4160.28 4114.58,4161.55 5012.13,4224.55 3529.45,4235.76 3411.13,4237.59 6288.36,4237.56 3258.15,4243.3 5232.69,4246.05 3221.2,4294.8 3464.92,4307.4 5009.17,4326.33 6130.15,4335.41 4436.21,4347.54 4746.34,4348.33 6288.36,4354.8 5187.1,4355.59 3561.25,4360.89 4290.08,4363.66 3250.89,4366.78 4584.77,4384.96 5012.13,4392.23 4371.1,4397.79 3189.36,4422.53 4243.9,4423.16 3252.21,4424.41 3554.4,4424.05 5222.78,4448.25 4290.08,4460.46 5013.36,4465.06 4240.99,4474.13 3363.6,4484.14 3506.08,4485.92 4580.92,4488.88 5913.79,4489.54 5661.9,4494.38 4736.02,4501.09 5190.21,4500.95 4368.88,4505.26 5764.93,4509.21 5533.86,4514.14 5944.08,4525.83 4245.68,4532.4 5615.69,4531.86 5994.47,4533.26 5826.5,4534.08 3503.93,4536.25 4288.31,4536.84 3382.58,4538.96 3297.98,4545.23 3459.5,4545.96 5481.39,4561.32 4577.32,4568.11 3297.98,4602.86 3460.17,4608.96 5060.02,4624.06 4692.19,4628.23 5262.89,4640.19 4577.32,4656.53 5471.9,4658.08 3301.33,4674.5 3747.34,4692.23 5476.62,4703.31 3531.17,4708.99 5828.15,4708.7 5475.08,4753.94 3532.55,4762.54 3605.58,4762.54 4585.36,4763.88 5827.97,4782 5399.37,4785.55 5676.24,4802.43 6125.88,4802.99 5509.36,4818.8 5572.62,4824.7 4372.15,4826.17 5509.36,4849.33 3255.26,4853.03 4598.39,4853.48 5676.24,4870.52 5572.74,4877.47 3388.48,4878.29 3507.29,4878.29 5509.36,4883.96 5116,4886.84 5829.74,4919.66 3746.99,4923.79 5536.31,4942.07 5587.6,4942.15 4360.86,4951.45 5680.39,4951.04 3345.43,4956.68 4435.35,4977.17 4501.58,4977.61 3269.05,4998.99 5809.94,4999.1 5067.13,5029.27 5191.32,5029.18 5126.72,5030.39 3193.78,5032.65 5564.71,5042.31 5673.28,5043.41 4680.74,5067.25 4734.94,5069.09 3346.84,5078.63 3452.5,5086.71 3748.16,5097.17 6123.88,5097.56 3265.53,5102.71 5127.86,5107.09 5064.31,5107.88 5676.17,5113.57 5559.38,5122.24 3501.75,5130.86 3653.09,5151.06 5088.78,5156.83 3105.54,5189.16 3444.04,5198.34 5561.01,5215.05 5681.5,5216.53 3540.75,5231.89 5813.57,5262.19 6130.99,5265.61 3104.35,5298.69 5163.46,5299.75 5822.52,5313.41 5241.76,5317.4 5563.37,5347.09 5676.17,5347.09 5786.3,5347.98 3531.67,5349.91 3445.37,5351.39 5200.15,5369.08 3076.24,5400.27 5559.58,5411.86 3463.63,5447.81 4937.6,5451.15 5025.23,5456.48 5827.27,5458.64 3358.24,5478.4 3079,5553.13 4523.34,5589.82 5099.47,5599.34 3166.21,5602.49 4431.37,5606.79 3187.53,5673.41 4677.34,5678.58 4830.99,5681.25 4973.09,5681.25 3692.06,5685.72 3081.44,5699.89 3566.6,5742.92 3403.39,6039.7 3517.08,6039.7
  other v3: 4531.97,4090.49 4171.97,4554.49 4376.06,4612.31 5948.42,4693.93 4161.47,4734.22 4372.65,4741.91 5905.62,4753.6 5948.42,4800.04 4222.15,4820.86 5198.71,4833.39 5905.62,4859.71 5198.1,4875.69 5948.42,4918.15 5167.89,4943.97 5905.62,4977.82 4619.09,5036.42 5948.42,5036.26 4423.91,5044.31 4498.08,5044.31 5905.62,5095.93 4451.46,5153.83 5951.18,5165.81 5905.62,5214.04 5948.42,5272.48 5905.62,5332.15 5954.38,5405.32
LD1: LD1.2 U6.10 | length 713.3
  Top Layer w6: U6.10@3319.67,4733.03 3319.67,4781.57 3339.92,4801.82 3509.92,4801.82 3519.92,4791.82 3615.92,4791.82 v1(3655.92,4831.82) ; LD1.2@3617.1,5113.03 3652.31,5077.82 v1(3655.92,5077.82)
  Bottom Layer w6: v1(3655.92,4831.82) v1(3655.92,5077.82)
LD2: LD2.2 U6.11 | length 613.2
  Top Layer w6: U6.11@3299.99,4733.03 3299.99,4787.88 3327.92,4815.82 3525.92,4815.82 3535.92,4805.82 3597.92,4805.82 v1(3621.92,4829.82) ; LD2.2@3618.06,5038.93 3619.92,5037.06 v1(3619.92,5003.82)
  Bottom Layer w6: v1(3619.92,5003.82) 3621.92,5001.82 v1(3621.92,4829.82)
LD3: LD3.2 U6.12 | length 534.1
  Top Layer w6: U6.12@3280.3,4733.03 3280.3,4802.2 3307.92,4829.82 v1(3589.92,4829.82) ; v1(3589.92,4927.82) 3589.92,4933.85 LD3.2@3618.1,4962.03
  Bottom Layer w6: v1(3589.92,4829.82) v1(3589.92,4927.82)
LD4: LD4.2 U6.19 | length 696.8
  Top Layer w6: U6.19@3221.25,4555.86 3255.97,4555.86 3271.92,4571.82 3271.92,4685.82 3255.92,4701.82 3255.92,4811.82 3291.92,4847.82 3579.85,4847.82 LD4.2@3618.06,4886.03
M-ATLK_RX: R48.1 U6.31 | length 470.7
  Top Layer w6: U6.31@3398.41,4398.38 3398.41,4332.34 3381.92,4315.85 3381.92,4214.86 3557.1,4039.68 R48.1@3557.1,4007.03
M-ATLK_TX: R47.1 U6.30 | length 448.5
  Top Layer w6: U6.30@3378.73,4398.38 3378.73,4336.66 3361.92,4319.85 3361.92,4162.2 3483.1,4041.03 R47.1@3483.1,4007.03
M-BOOT0: J9.2 U6.44 | length 154.6
  Top Layer w6: U6.44@3555.9,4595.23 3627.3,4595.23 J9.2@3686.1,4654.03
M-NRST: C22.2 P1.4 U6.7 | length 957
  Top Layer w6: v1(3393.92,4781.82) 3378.73,4766.62 U6.7@3378.73,4733.03 3378.73,4651.01 3384.73,4645.01 3384.73,4575.37 3521.92,4438.17 v1(3521.92,4355.82)
  Bottom Layer w6: v2(3384.73,4636.07) 3385.42,4635.38 C22.2@3423.92,4635.38 ; v1(3521.92,4355.82) 3561.92,4315.82 3561.92,4078.2 P1.4@3655.1,3985.03
M-SWCLK: P1.3 U6.37 | length 447.4
  Top Layer w6: U6.37@3555.9,4457.43 3588.31,4457.43 v1(3605.92,4439.82)
  Bottom Layer w6: v1(3605.92,4439.82) 3605.92,4367.82 3587.92,4349.82 3587.92,4152.2 P1.3@3655.1,4085.03
M-SWDIO: P1.2 U6.34 | length 311.8
  Top Layer w6: U6.34@3457.47,4398.38 3457.47,4354.27 3626.72,4185.03 P1.2@3655.1,4185.03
